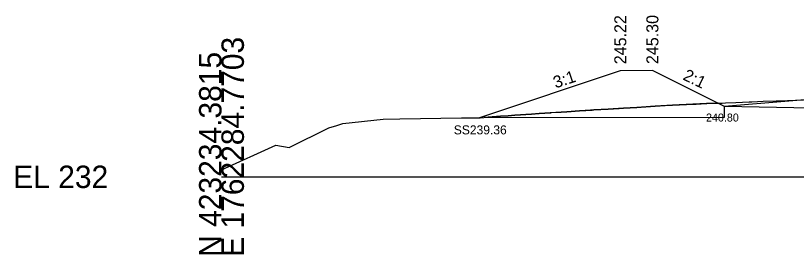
# Model space of a CAD drawing. Extents: x -26 to 3203, y -11010 to 4024.
# Drawn here: x -25.7 to 71.8, y 990.3 to 1020.1 of the extents above; entities that cross this region are included whole.
import ezdxf

# ---------------------------------------------------------------- set-up
doc = ezdxf.new("R2010")
doc.units = 0
for name, color, linetype in [('Default', 7, 'Continuous'), ('Exist Cross Section Cell', 7, 'Continuous'), ('Exist XS Ground Line', 7, 'Continuous'), ('Prop CMT Slope Grass', 7, 'Continuous'), ('Prop CMT Subgrade Earthwork', 7, 'Continuous'), ('Prop CMT Undercut', 7, 'Continuous'), ('Prop CMT Undercut Boundary', 7, 'Continuous'), ('Prop XS Hydro Elevations', 7, 'Continuous'), ('Prop XS Side Slope Text', 7, 'Continuous'), ('Prop XS SS Elevation Text', 7, 'Continuous'), ('Scratch_Level_0', 7, 'Continuous')]:
    doc.layers.add(name, color=color, linetype=linetype)

msp = doc.modelspace()

# ---------------------------------------------------------------- linework, layer by layer
at = {"layer": 'Exist Cross Section Cell'}
msp.add_line((0, 1000), (100, 1000), dxfattribs=at)
at = {"layer": 'Exist XS Ground Line'}
msp.add_lwpolyline([(0, 1000.871), (6.778, 1003.972), (8.434, 1003.66), (13.411, 1006.132), (14.4, 1006.404), (15.139, 1006.654), (20.179, 1007.204), (22.249, 1007.26), (29.962, 1007.368), (32.184, 1007.362), (32.268, 1007.369), (32.761, 1007.408), (33.519, 1007.469), (34.841, 1007.565), (35.79, 1007.636), (36.623, 1007.697), (38.702, 1007.845), (39.631, 1007.908), (41.126, 1008.008), (41.203, 1008.017), (42.383, 1008.085), (42.759, 1008.108), (43.095, 1008.128), (44.67, 1008.227), (46.257, 1008.337), (46.47, 1008.351), (48.263, 1008.459), (49.652, 1008.537), (50.166, 1008.565), (51.844, 1008.663), (52.965, 1008.749), (54.135, 1008.827), (55.384, 1008.899), (56.3, 1008.948), (58.042, 1009.03), (59.255, 1009.086), (60.549, 1009.141), (60.582, 1009.142), (61.943, 1009.196), (62.486, 1009.22), (62.898, 1009.236), (64.179, 1009.289), (65.87, 1009.358), (66.039, 1009.365), (66.176, 1009.372), (66.181, 1009.372), (67.626, 1009.441), (69.245, 1009.498), (69.383, 1009.503), (69.495, 1009.507), (69.628, 1009.511), (72.626, 1009.6)], dxfattribs=at)
msp.add_lwpolyline([(0, 1000.871), (6.778, 1003.972), (8.434, 1003.66), (13.411, 1006.132), (14.4, 1006.404), (15.139, 1006.654), (20.179, 1007.204), (22.249, 1007.26), (29.962, 1007.368), (32.184, 1007.362), (32.268, 1007.369), (32.761, 1007.408), (33.519, 1007.469), (34.841, 1007.565), (35.79, 1007.636), (36.623, 1007.697), (38.702, 1007.845), (39.631, 1007.908), (41.126, 1008.008), (41.203, 1008.017), (42.383, 1008.085), (42.759, 1008.108), (43.095, 1008.128), (44.67, 1008.227), (46.257, 1008.337), (46.47, 1008.351), (48.263, 1008.459), (49.652, 1008.537), (50.166, 1008.565), (51.844, 1008.663), (52.965, 1008.749), (54.135, 1008.827), (55.384, 1008.899), (56.3, 1008.948), (58.042, 1009.03), (59.255, 1009.086), (60.549, 1009.141), (60.582, 1009.142), (61.943, 1009.196), (62.486, 1009.22), (62.898, 1009.236), (64.179, 1009.289), (65.87, 1009.358), (66.039, 1009.365), (66.176, 1009.372), (66.181, 1009.372), (67.626, 1009.441), (69.245, 1009.498), (69.383, 1009.503), (69.495, 1009.507), (69.628, 1009.511), (72.626, 1009.6)], dxfattribs=at)
msp.add_lwpolyline([(0, 1000.871), (6.778, 1003.972), (8.434, 1003.66), (13.411, 1006.132), (14.4, 1006.404), (15.139, 1006.654), (20.179, 1007.204), (22.249, 1007.26), (29.962, 1007.368), (32.184, 1007.362), (32.268, 1007.369), (32.761, 1007.408), (33.519, 1007.469), (34.841, 1007.565), (35.79, 1007.636), (36.623, 1007.697), (38.702, 1007.845), (39.631, 1007.908), (41.126, 1008.008), (41.203, 1008.017), (42.383, 1008.085), (42.759, 1008.108), (43.095, 1008.128), (44.67, 1008.227), (46.257, 1008.337), (46.47, 1008.351), (48.263, 1008.459), (49.652, 1008.537), (50.166, 1008.565), (51.844, 1008.663), (52.965, 1008.749), (54.135, 1008.827), (55.384, 1008.899), (56.3, 1008.948), (58.042, 1009.03), (59.255, 1009.086), (60.549, 1009.141), (60.582, 1009.142), (61.943, 1009.196), (62.486, 1009.22), (62.898, 1009.236), (64.179, 1009.289), (65.87, 1009.358), (66.039, 1009.365), (66.176, 1009.372), (66.181, 1009.372), (67.626, 1009.441), (69.245, 1009.498), (69.383, 1009.503), (69.495, 1009.507), (69.628, 1009.511), (72.626, 1009.6)], dxfattribs=at)
msp.add_lwpolyline([(0, 1000.871), (6.778, 1003.972), (8.434, 1003.66), (13.411, 1006.132), (14.4, 1006.404), (15.139, 1006.654), (20.179, 1007.204), (22.249, 1007.26), (29.962, 1007.368), (32.184, 1007.362), (32.268, 1007.369), (32.761, 1007.408), (33.519, 1007.469), (34.841, 1007.565), (35.79, 1007.636), (36.623, 1007.697), (38.702, 1007.845), (39.631, 1007.908), (41.126, 1008.008), (41.203, 1008.017), (42.383, 1008.085), (42.759, 1008.108), (43.095, 1008.128), (44.67, 1008.227), (46.257, 1008.337), (46.47, 1008.351), (48.263, 1008.459), (49.652, 1008.537), (50.166, 1008.565), (51.844, 1008.663), (52.965, 1008.749), (54.135, 1008.827), (55.384, 1008.899), (56.3, 1008.948), (58.042, 1009.03), (59.255, 1009.086), (60.549, 1009.141), (60.582, 1009.142), (61.943, 1009.196), (62.486, 1009.22), (62.898, 1009.236), (64.179, 1009.289), (65.87, 1009.358), (66.039, 1009.365), (66.176, 1009.372), (66.181, 1009.372), (67.626, 1009.441), (69.245, 1009.498), (69.383, 1009.503), (69.495, 1009.507), (69.628, 1009.511), (72.626, 1009.6)], dxfattribs=at)
msp.add_lwpolyline([(0, 1000.871), (6.778, 1003.972), (8.434, 1003.66), (13.411, 1006.132), (14.4, 1006.404), (15.139, 1006.654), (20.179, 1007.204), (22.249, 1007.26), (29.962, 1007.368), (32.184, 1007.362), (32.268, 1007.369), (32.761, 1007.408), (33.519, 1007.469), (34.841, 1007.565), (35.79, 1007.636), (36.623, 1007.697), (38.702, 1007.845), (39.631, 1007.908), (41.126, 1008.008), (41.203, 1008.017), (42.383, 1008.085), (42.759, 1008.108), (43.095, 1008.128), (44.67, 1008.227), (46.257, 1008.337), (46.47, 1008.351), (48.263, 1008.459), (49.652, 1008.537), (50.166, 1008.565), (51.844, 1008.663), (52.965, 1008.749), (54.135, 1008.827), (55.384, 1008.899), (56.3, 1008.948), (58.042, 1009.03), (59.255, 1009.086), (60.549, 1009.141), (60.582, 1009.142), (61.943, 1009.196), (62.486, 1009.22), (62.898, 1009.236), (64.179, 1009.289), (65.87, 1009.358), (66.039, 1009.365), (66.176, 1009.372), (66.181, 1009.372), (67.626, 1009.441), (69.245, 1009.498), (69.383, 1009.503), (69.495, 1009.507), (69.628, 1009.511), (72.626, 1009.6)], dxfattribs=at)
at = {"layer": 'Prop CMT Slope Grass'}
msp.add_lwpolyline([(74.8, 1009.764), (70.8, 1009.444), (62.78, 1008.802), (53.78, 1013.302), (49.78, 1013.222), (32.205, 1007.364)], dxfattribs=at)
at = {"layer": 'Prop CMT Subgrade Earthwork'}
msp.add_lwpolyline([(73.61, 1008.573), (62.78, 1008.802)], dxfattribs=at)
at = {"layer": 'Prop CMT Undercut'}
msp.add_lwpolyline([(32.761, 1007.408), (62.78, 1007.44), (62.78, 1008.802), (61.987, 1009.198), (61.943, 1009.196), (60.549, 1009.141), (56.3, 1008.948), (54.135, 1008.827), (51.844, 1008.663), (50.166, 1008.565), (48.263, 1008.459), (46.47, 1008.351), (46.041, 1008.322), (44.67, 1008.227), (43.095, 1008.128), (39.63, 1007.908), (38.702, 1007.845), (36.623, 1007.697), (35.79, 1007.636), (34.841, 1007.565)], close=True, dxfattribs=at)
at = {"layer": 'Prop CMT Undercut Boundary'}
msp.add_lwpolyline([(32.761, 1007.408), (62.78, 1007.44), (62.78, 1008.802), (61.987, 1009.198), (61.943, 1009.196), (60.549, 1009.141), (56.3, 1008.948), (54.135, 1008.827), (51.844, 1008.663), (50.166, 1008.565), (48.263, 1008.459), (46.47, 1008.351), (46.041, 1008.322), (44.67, 1008.227), (43.095, 1008.128), (39.63, 1007.908), (38.702, 1007.845), (36.623, 1007.697), (35.79, 1007.636), (34.841, 1007.565), (32.761, 1007.408), (32.761, 1007.408), (32.761, 1007.408)], dxfattribs=at)

# ---------------------------------------------------------------- texts
at = {"layer": 'Default'}
msp.add_text('-', height=0.0001, dxfattribs=at).set_placement((0, 1000))
msp.add_text('-', height=0.0001, dxfattribs=at).set_placement((0, 1000))
at = {"layer": 'Exist Cross Section Cell'}
for s, p in [('E 1762284.7703', (2.8, 990)), ('N 423234.3815', (0, 990))]:
    msp.add_text(s, height=2.8, rotation=90, dxfattribs=at).set_placement(p)
msp.add_text('EL 232', height=2.8, dxfattribs=at).set_placement((-26, 998.6))
at = {"layer": 'Prop XS Hydro Elevations'}
for s, p in [('245.22', (50.53, 1014.062)), ('245.30', (54.53, 1014.084))]:
    msp.add_text(s, height=1.5, rotation=90, dxfattribs=at).set_placement(p)
at = {"layer": 'Prop XS Side Slope Text'}
for s, rotation, p in [('3:1', 18.43493, (41.7, 1011.034)), ('2:1', 334.09695, (57.49, 1012.194))]:
    msp.add_text(s, height=1.5, rotation=rotation, dxfattribs=at).set_placement(p)
at = {"layer": 'Prop XS SS Elevation Text'}
for s, height, p in [('240.80', 1.0001, (60.474, 1006.905)), ('SS239.36', 1.125, (28.994, 1005.301))]:
    msp.add_text(s, height=height, dxfattribs=at).set_placement(p)
at = {"layer": 'Scratch_Level_0'}
for s, p in [('LT_Berm_Top out', (49.638, 1013.212)), ('LT_Berm_Top in', (53.654, 1013.292)), ('LT_Ditch_Bot', (62.675, 1008.792)), ('LT_GS_OS_CTL', (70.695, 1009.434)), ('Exterior Boundary', (32.046, 1007.354)), ('LT_Slope_Fill', (32.111, 1007.354))]:
    msp.add_text(s, height=0.02, dxfattribs=at).set_placement(p)

doc.saveas('drawing.dxf')
